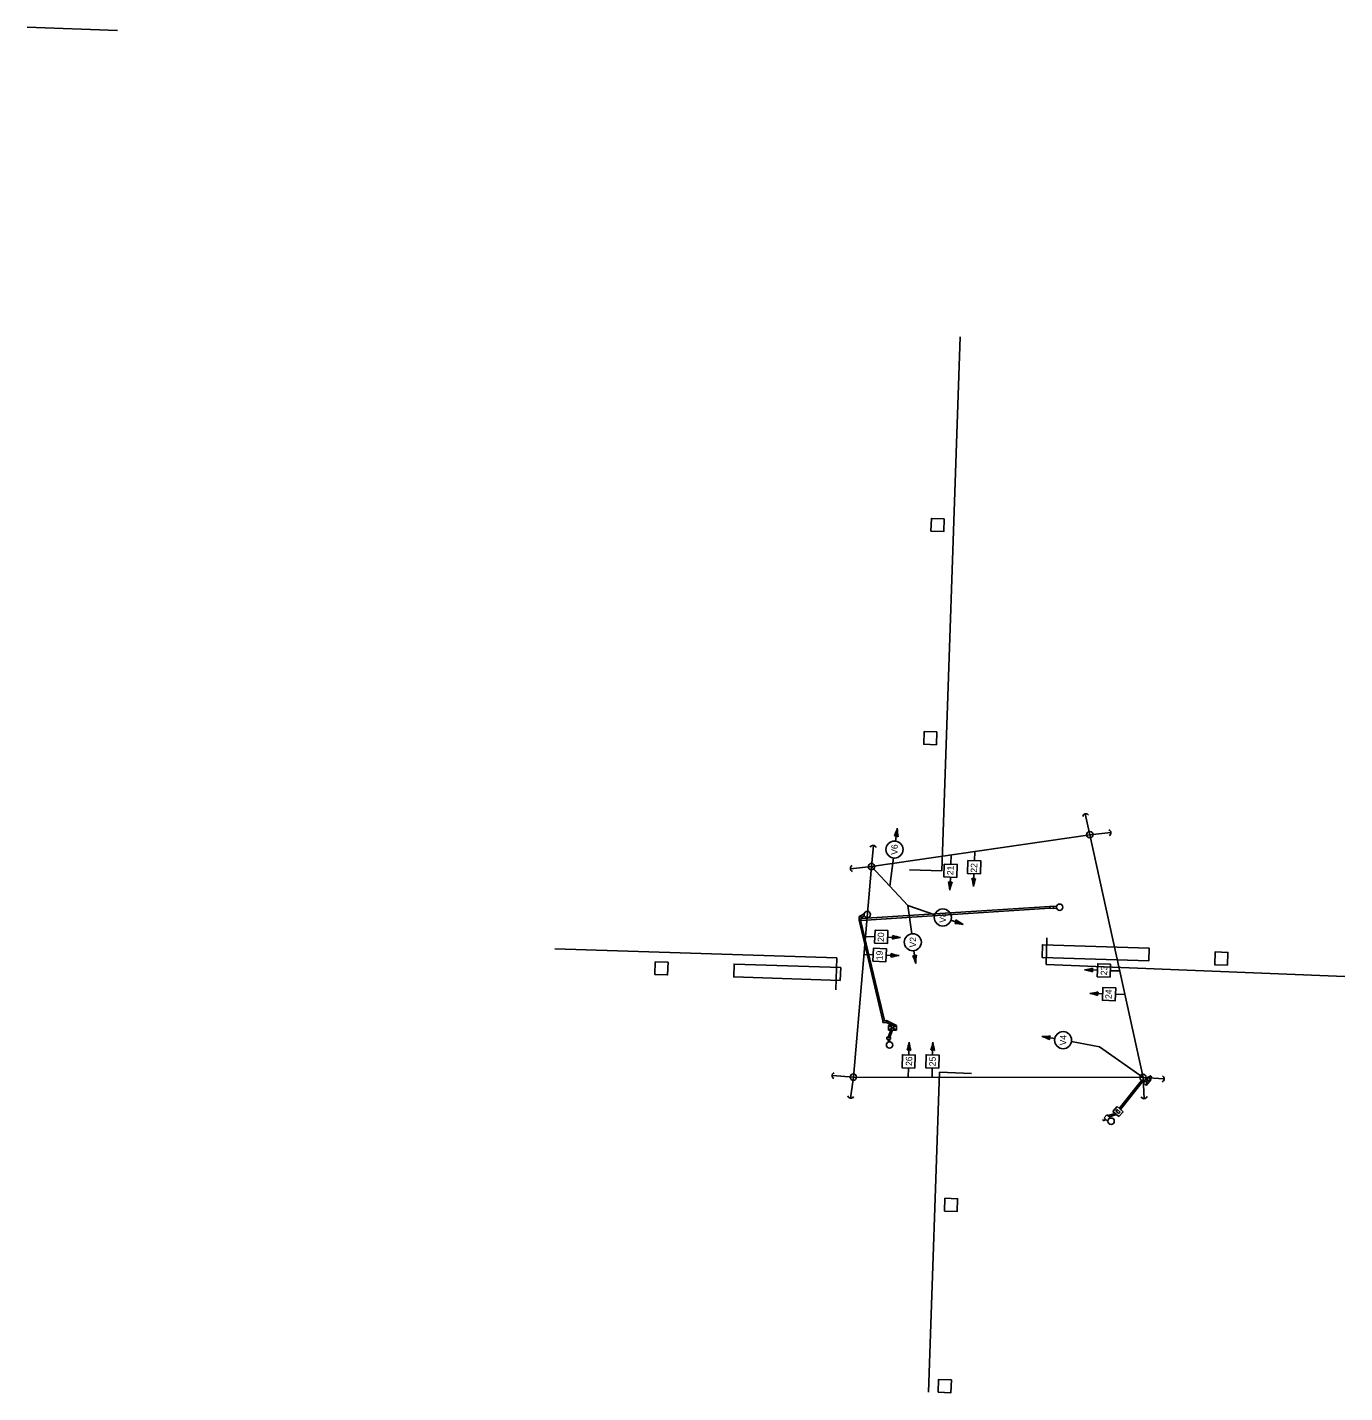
# Model space of a CAD drawing. Extents: x 982100 to 1292532, y 220574 to 1843876.
# Drawn here: x 992068 to 992685, y 1843188 to 1843828 of the extents above; entities that cross this region are included whole.
import ezdxf

# ---------------------------------------------------------------- set-up
doc = ezdxf.new("R2010")
doc.units = 0
for name, color, linetype in [('No Plot', 7, 'Continuous'), ('R_Existing Signal', 7, 'Continuous'), ('R_Striping', 7, 'Continuous'), ('T_Drafting', 7, 'Continuous'), ('T_Indications', 7, 'Continuous'), ('V-SIGNAL-CONDUIT', 7, 'Continuous'), ('V-SIGNAL-HEAD-MOT', 7, 'Continuous'), ('V-SIGNAL-LOOP-MOT', 7, 'Continuous'), ('V-SIGNAL-POLE', 7, 'Continuous'), ('V-SIGNAL-POLE-MOT', 7, 'Continuous')]:
    doc.layers.add(name, color=color, linetype=linetype)

msp = doc.modelspace()

# ---------------------------------------------------------------- linework, layer by layer
at = {"layer": 'No Plot'}
msp.add_line((992109.76, 1843826.41), (992067.51, 1843827.86), dxfattribs=at)
at = {"layer": 'R_Existing Signal'}
for p, q in [((992458.41, 1843409.19), (992546.91, 1843414.88)), ((992458.43, 1843410.07), (992546.96, 1843415.63)), ((992546.98, 1843415.83), (992546.92, 1843414.91)), ((992546.92, 1843414.91), (992548.66, 1843414.79)), ((992548.72, 1843415.71), (992546.98, 1843415.83)), ((992548.66, 1843414.79), (992548.72, 1843415.71)), ((992548.66, 1843414.79), (992550.16, 1843414.89)), ((992548.72, 1843415.71), (992550.15, 1843415.8)), ((992457.54, 1843410.97), (992457.49, 1843409.22)), ((992457.49, 1843409.22), (992458.41, 1843409.19)), ((992457.49, 1843409.22), (992468.67, 1843362.15)), ((992457.54, 1843410.97), (992459.9, 1843412.24)), ((992458.46, 1843410.94), (992457.54, 1843410.97)), ((992458.25, 1843409.2), (992469.43, 1843362.16)), ((992458.41, 1843409.19), (992458.46, 1843410.94)), ((992458.44, 1843410.43), (992459.98, 1843411.3)), ((992470.42, 1843362.16), (992468.67, 1843362.15)), ((992468.67, 1843362.15), (992468.67, 1843361.24)), ((992468.67, 1843361.24), (992470.42, 1843361.24)), ((992470.42, 1843361.24), (992470.42, 1843362.16)), ((992475, 1843359.93), (992470.42, 1843362.16)), ((992473.31, 1843359.93), (992470.42, 1843361.33)), ((992471.16, 1843354.42), (992472.36, 1843357.68)), ((992471.34, 1843359.93), (992475, 1843359.93)), ((992471.34, 1843357.68), (992475, 1843359.93)), ((992471.34, 1843359.93), (992475, 1843357.68)), ((992471.34, 1843357.68), (992471.34, 1843359.93)), ((992471.34, 1843357.68), (992475, 1843357.68)), ((992471.95, 1843354.42), (992473.15, 1843357.68)), ((992475, 1843357.68), (992475, 1843359.93)), ((992472.31, 1843354.38), (992470.56, 1843354.38)), ((992470.56, 1843354.38), (992470.57, 1843353.46)), ((992470.57, 1843353.46), (992472.32, 1843353.47)), ((992471.24, 1843352.13), (992471.06, 1843353.47)), ((992471.98, 1843352.23), (992471.81, 1843353.47)), ((992472.32, 1843353.47), (992472.31, 1843354.38))]:
    msp.add_line(p, q, dxfattribs=at)
for centre in [(992551.58, 1843415.35), (992461.36, 1843411.89), (992471.8, 1843350.74)]:
    msp.add_circle(centre, 1.5, dxfattribs=at)
at = {"layer": 'R_Striping'}
for p, q in [((992496.35, 1843432.44), (992504.94, 1843682.79)), ((992481.23, 1843432.85), (992496.35, 1843432.44)), ((992447.05, 1843391.61), (992314.8, 1843395.84)), ((992545.63, 1843400.95), (992545.23, 1843388.46)), ((992447.05, 1843391.6), (992446.58, 1843376.63)), ((992685.22, 1843382.85), (992545.23, 1843388.46)), ((992490.11, 1843188.05), (992495.25, 1843337.96)), ((992495.25, 1843337.96), (992510.25, 1843337.46))]:
    msp.add_line(p, q, dxfattribs=at)
at = {"layer": 'T_Drafting'}
for p, q in [((992590.54, 1843333.14), (992592.96, 1843335.9)), ((992592.11, 1843331.77), (992590.54, 1843333.14)), ((992590.55, 1843333.15), (992594.52, 1843334.53)), ((992592.96, 1843335.9), (992592.1, 1843331.77)), ((992592.11, 1843331.77), (992594.52, 1843334.53)), ((992594.52, 1843334.53), (992592.96, 1843335.9)), ((992573.69, 1843318.06), (992572.38, 1843316.55)), ((992573.69, 1843318.06), (992575.2, 1843316.75)), ((992571.72, 1843315.8), (992572.48, 1843315.14)), ((992572.38, 1843316.55), (992573.89, 1843315.24)), ((992573.13, 1843315.9), (992572.48, 1843315.14)), ((992575.2, 1843316.75), (992573.89, 1843315.24))]:
    msp.add_line(p, q, dxfattribs=at)
msp.add_lwpolyline([(992593.36, 1843335.54), (992594.02, 1843336.3), (992594.77, 1843335.64), (992594.11, 1843334.89)], close=True, dxfattribs=at)
msp.add_circle((992575.68, 1843315.01), 1.5, dxfattribs=at)
at = {"layer": 'T_Indications'}
for p, q in [((992474.65, 1843446.35), (992475.44, 1843452.36)), ((992500.66, 1843439.84), (992500.51, 1843435.5)), ((992511.72, 1843441.46), (992511.57, 1843437.11)), ((992500.32, 1843429.44), (992500.1, 1843423.4)), ((992511.38, 1843431.05), (992511.16, 1843425.02)), ((992500.58, 1843409.25), (992506.32, 1843407.31)), ((992460.54, 1843401.67), (992464.89, 1843401.52)), ((992470.95, 1843401.33), (992476.98, 1843401.12)), ((992483.25, 1843394.96), (992484.06, 1843388.95)), ((992459.81, 1843393.19), (992464.15, 1843393.04)), ((992470.21, 1843392.85), (992476.25, 1843392.63)), ((992569.29, 1843385.78), (992563.26, 1843385.99)), ((992579.7, 1843385.44), (992575.35, 1843385.59)), ((992571.72, 1843374.72), (992565.68, 1843374.93)), ((992582.12, 1843374.38), (992577.78, 1843374.53)), ((992480.85, 1843346.09), (992481.02, 1843352.12)), ((992491.98, 1843346.07), (992492.14, 1843352.11)), ((992549.26, 1843353.72), (992543.29, 1843354.79)), ((992480.6, 1843335.68), (992480.71, 1843340.03)), ((992491.72, 1843335.67), (992491.84, 1843340.01))]:
    msp.add_line(p, q, dxfattribs=at)
for points in [[(992497.49, 1843435.6), (992503.55, 1843435.39), (992503.34, 1843429.33), (992497.28, 1843429.54)], [(992508.55, 1843437.22), (992514.61, 1843437.01), (992514.4, 1843430.95), (992508.34, 1843431.16)], [(992464.78, 1843398.51), (992464.99, 1843404.57), (992471.05, 1843404.35), (992470.84, 1843398.29)], [(992464.04, 1843390.02), (992464.26, 1843396.09), (992470.32, 1843395.87), (992470.1, 1843389.81)], [(992575.46, 1843388.61), (992575.25, 1843382.55), (992569.19, 1843382.76), (992569.4, 1843388.82)], [(992577.88, 1843377.55), (992577.67, 1843371.49), (992571.61, 1843371.7), (992571.83, 1843377.76)], [(992483.73, 1843339.94), (992477.67, 1843340.11), (992477.83, 1843346.17), (992483.89, 1843346)], [(992494.86, 1843339.93), (992488.8, 1843340.09), (992488.96, 1843346.15), (992495.02, 1843345.99)]]:
    msp.add_lwpolyline(points, close=True, dxfattribs=at)
for centre in [(992474.13, 1843442.38), (992496.79, 1843410.53), (992482.71, 1843398.92), (992553.19, 1843353.01)]:
    msp.add_circle(centre, 4, dxfattribs=at)
for centre, radius, start, end in [((992447.12, 1843460.52), 29.47, 336.19694, 343.93506), ((992474.75, 1843447.14), 1.63, 50.69606, 114.39069), ((992504.9, 1843452.96), 29.47, 181.15169, 188.8898), ((992500.29, 1843428.66), 1.63, 236.1222, 299.81684), ((992470.82, 1843420.02), 29.47, 6.57783, 14.31595), ((992529.07, 1843417.96), 29.47, 161.62309, 169.3612), ((992511.35, 1843430.28), 1.63, 236.1222, 299.81684), ((992481.88, 1843421.64), 29.47, 6.57783, 14.31595), ((992540.13, 1843419.58), 29.47, 161.62309, 169.3612), ((992501.33, 1843409), 1.63, 309.48666, 13.1813), ((992501.17, 1843378.29), 29.47, 79.9423, 87.68041), ((992519.83, 1843433.51), 29.47, 234.98755, 242.72566), ((992471.72, 1843401.3), 1.63, 326.12483, 29.81946), ((992482.42, 1843430.08), 29.47, 251.62571, 259.36383), ((992480.36, 1843371.84), 29.47, 96.58046, 104.31857), ((992470.98, 1843392.82), 1.63, 326.12483, 29.81946), ((992479.63, 1843363.36), 29.47, 96.58046, 104.31857), ((992481.69, 1843421.6), 29.47, 251.62571, 259.36383), ((992483.36, 1843394.17), 1.63, 245.85569, 309.55033), ((992455.78, 1843380.67), 29.47, 16.31133, 24.04944), ((992513.53, 1843388.48), 29.47, 171.35658, 179.09469), ((992559.87, 1843415.27), 29.47, 276.60812, 284.34623), ((992557.83, 1843357.02), 29.47, 71.65337, 79.39148), ((992568.52, 1843385.81), 1.63, 146.15248, 209.84712), ((992562.29, 1843404.21), 29.47, 276.60812, 284.34623), ((992570.95, 1843374.75), 1.63, 146.15248, 209.84712), ((992560.26, 1843345.97), 29.47, 71.65337, 79.39148), ((992452.01, 1843357.32), 29.47, 342.10567, 349.84378), ((992510.27, 1843355.75), 29.47, 187.06041, 194.79853), ((992463.14, 1843357.31), 29.47, 342.10567, 349.84378), ((992521.39, 1843355.73), 29.47, 187.06041, 194.79853), ((992544.09, 1843384.25), 29.47, 268.43172, 276.16983), ((992533.8, 1843326.89), 29.47, 63.47697, 71.21509), ((992548.47, 1843353.86), 1.63, 137.97609, 201.67072), ((992480.88, 1843346.86), 1.63, 56.60478, 120.29942), ((992492, 1843346.85), 1.63, 56.60478, 120.29942)]:
    msp.add_arc(centre, radius, start, end, dxfattribs=at)
at = {"layer": 'V-SIGNAL-CONDUIT'}
for p, q in [((992579.48, 1843320.97), (992590.02, 1843334.17)), ((992580.04, 1843320.48), (992590.87, 1843334.05)), ((992577.64, 1843318.7), (992574.1, 1843317.7)), ((992578.31, 1843318.11), (992574.78, 1843317.11)), ((992576.57, 1843319.64), (992578.49, 1843321.84)), ((992579.39, 1843317.17), (992576.57, 1843319.64)), ((992577.98, 1843319.74), (992578.58, 1843320.43)), ((992579.29, 1843318.59), (992577.98, 1843319.74)), ((992578.49, 1843321.84), (992581.31, 1843319.37)), ((992578.58, 1843320.43), (992579.9, 1843319.28)), ((992579.9, 1843319.28), (992579.29, 1843318.59)), ((992581.31, 1843319.37), (992579.39, 1843317.17))]:
    msp.add_line(p, q, dxfattribs=at)
at = {"layer": 'V-SIGNAL-LOOP-MOT'}
for points in [[(992497.44, 1843597.44), (992491.45, 1843597.65), (992491.24, 1843591.65), (992497.24, 1843591.44)], [(992494.02, 1843497.5), (992488.02, 1843497.71), (992487.82, 1843491.71), (992493.81, 1843491.5)], [(992593.31, 1843390.18), (992593.5, 1843396.17), (992543.52, 1843397.77), (992543.33, 1843391.77)], [(992361.95, 1843389.77), (992361.76, 1843383.77), (992367.75, 1843383.58), (992367.95, 1843389.58)], [(992448.72, 1843381.05), (992448.91, 1843387.05), (992398.93, 1843388.65), (992398.74, 1843382.65)], [(992630.26, 1843388.2), (992630.45, 1843394.19), (992624.46, 1843394.39), (992624.27, 1843388.39)], [(992497.53, 1843272.9), (992503.52, 1843272.69), (992503.73, 1843278.69), (992497.73, 1843278.89)], [(992494.61, 1843187.95), (992500.61, 1843187.74), (992500.81, 1843193.74), (992494.82, 1843193.94)]]:
    msp.add_lwpolyline(points, close=True, dxfattribs=at)
at = {"layer": 'V-SIGNAL-POLE'}
for p, q in [((992473.61, 1843438.42), (992471.89, 1843425.23)), ((992493, 1843411.81), (992480.39, 1843416.07)), ((992482.18, 1843402.89), (992480.39, 1843416.07)), ((992557.13, 1843352.31), (992570.22, 1843349.96))]:
    msp.add_line(p, q, dxfattribs=at)
at = {"layer": 'V-SIGNAL-POLE-MOT'}
for p, q in [((992563.54, 1843459.12), (992565.68, 1843449.35)), ((992463.38, 1843434.38), (992565.68, 1843449.35)), ((992575.63, 1843450.38), (992565.68, 1843449.35)), ((992565.68, 1843449.35), (992590.65, 1843335.54)), ((992464.24, 1843444.35), (992463.38, 1843434.38)), ((992453.43, 1843433.35), (992463.38, 1843434.38)), ((992454.83, 1843335.71), (992463.38, 1843434.38)), ((992480.39, 1843416.07), (992463.38, 1843434.38)), ((992590.65, 1843335.54), (992570.22, 1843349.96)), ((992444.85, 1843336.43), (992454.83, 1843335.71)), ((992453.45, 1843325.81), (992454.83, 1843335.71)), ((992590.65, 1843335.54), (992454.83, 1843335.71)), ((992600.62, 1843334.82), (992590.65, 1843335.54)), ((992591.22, 1843325.55), (992590.65, 1843335.54))]:
    msp.add_line(p, q, dxfattribs=at)
for centre in [(992565.68, 1843449.35), (992463.38, 1843434.38), (992454.83, 1843335.71), (992590.65, 1843335.54)]:
    msp.add_circle(centre, 1.5, dxfattribs=at)
for centre, start, end in [((992563.86, 1843457.66), 34.87201, 169.87201), ((992574.13, 1843450.23), 298.40614, 73.40614), ((992464.11, 1843442.85), 17.54822, 152.54822), ((992454.92, 1843433.51), 118.40614, 253.40614), ((992446.35, 1843336.33), 108.37023, 243.37023), ((992599.12, 1843334.92), 288.37023, 63.37023), ((992453.66, 1843327.29), 194.602, 329.602), ((992591.13, 1843327.05), 205.78453, 340.78453)]:
    msp.add_arc(centre, 1.5, start, end, dxfattribs=at)

# ---------------------------------------------------------------- texts
at = {"layer": 'V-SIGNAL-HEAD-MOT'}
for s, rotation, p in [('V6', 88.03611, (992475.55, 1843439.87)), ('21', 88.18457, (992501.73, 1843430.33)), ('22', 88.18457, (992512.81, 1843431.49)), ('V8', 88.03611, (992498.2, 1843408.01)), ('20', 88.26661, (992469.16, 1843399.05)), ('19', 88.26661, (992468.53, 1843390.47)), ('V2', 88.03611, (992484.13, 1843396.42)), ('23', 88.30022, (992573.81, 1843383.4)), ('24', 88.30022, (992575.93, 1843372.29)), ('V4', 88.03611, (992554.61, 1843350.5)), ('26', 88.54492, (992482.37, 1843340.89)), ('25', 88.54492, (992493.4, 1843340.75))]:
    msp.add_text(s, height=3, rotation=rotation, dxfattribs=at).set_placement(p)

doc.saveas('drawing.dxf')
